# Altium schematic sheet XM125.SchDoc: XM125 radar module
size 420 x 297 mm; CompanyName: Acconeer AB; DrawnBy: Jonas Långbacka; Address1: Acconeer AB; Address2: Västra Varvsgatan 19; Address3: 211 77 Malmö; Address4: Sweden; SheetNumber: 1; SheetTotal: 1
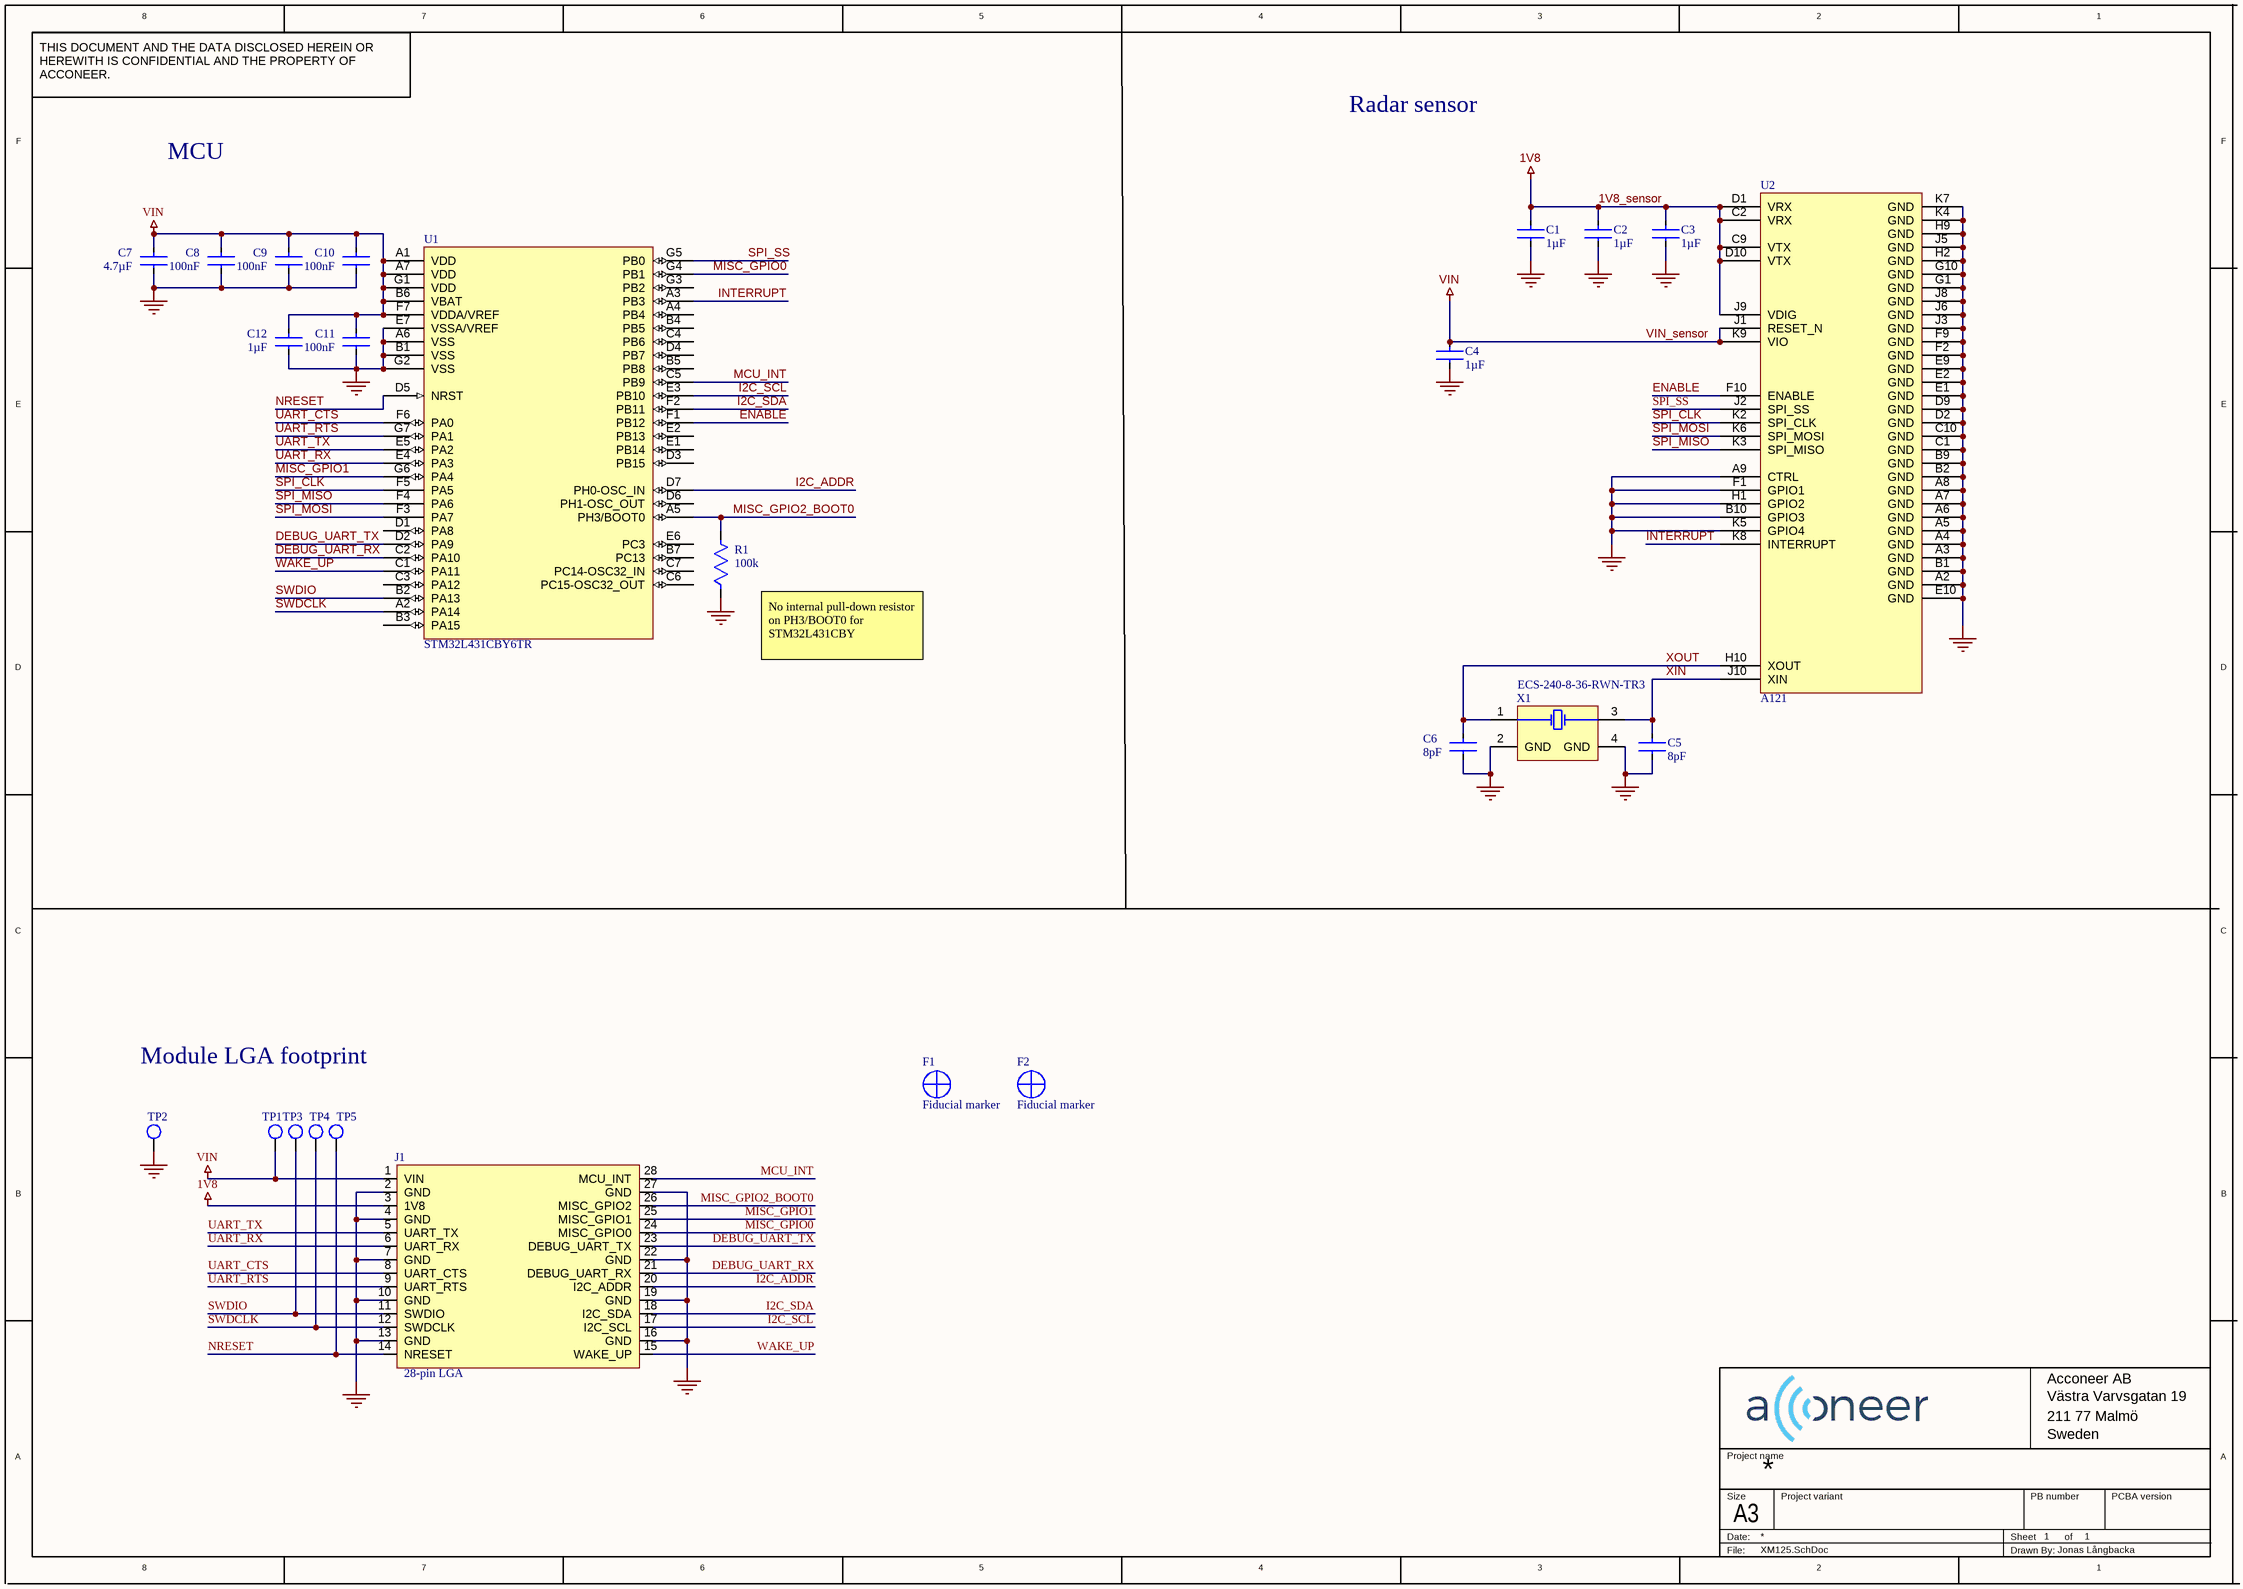
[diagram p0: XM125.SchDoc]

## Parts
C1  value 1µF  [CAPC0603X04L_no_silkscreen]  (hidden comment: Capacitor 1uF, metric 0603)
C2  value 1µF  [CAPC0603X04L_no_silkscreen]  (hidden comment: Capacitor 1uF, metric 0603)
C3  value 1µF  [CAPC0603X04L_no_silkscreen]  (hidden comment: Capacitor 1uF, metric 0603)
C4  value 1µF  [CAPC0603X04L_no_silkscreen]  (hidden comment: Capacitor 1uF, metric 0603)
C5  value 8pF  [CAPC0603X04L_no_silkscreen]  (hidden comment: Capacitor 8pF, metric 0603)
C6  value 8pF  [CAPC0603X04L_no_silkscreen]  (hidden comment: Capacitor 8pF, metric 0603)
C7  value 4.7µF  [CAPC1005X05L]  (hidden comment: Capacitor 4.7uF, metric 1005)
C8  value 100nF  [CAPC0603X04L_no_silkscreen]  (hidden comment: Capacitor 100nF, metric 0603)
C9  value 100nF  [CAPC0603X04L_no_silkscreen]  (hidden comment: Capacitor 100nF, metric 0603)
C10  value 100nF  [CAPC0603X04L_no_silkscreen]  (hidden comment: Capacitor 100nF, metric 0603)
C11  value 100nF  [CAPC0603X04L_no_silkscreen]  (hidden comment: Capacitor 100nF, metric 0603)
C12  value 1µF  [CAPC0603X04L_no_silkscreen]  (hidden comment: Capacitor 1uF, metric 0603)
F1  Fiducial marker  [Fiducial 0.5 mm footprint-1]  (no BOM)
F2  Fiducial marker  [Fiducial 0.5 mm footprint-1]  (no BOM)
J1  28-pin LGA  [LCCS127P1500X1800X0-28N]  (no BOM)
R1  value 100k  [RESC0603X03L_no_silkscreen]  (hidden comment: Resistor 100 kOhm, metric 0603)
TP1  Testpoint  [Testpoint_circular_0.8_no_silkscreen]  (value not drawn)  (no BOM)
TP2  Testpoint  [Testpoint_circular_0.8_no_silkscreen]  (value not drawn)  (no BOM)
TP3  Testpoint  [Testpoint_circular_0.8_no_silkscreen]  (value not drawn)  (no BOM)
TP4  Testpoint  [Testpoint_circular_0.8_no_silkscreen]  (value not drawn)  (no BOM)
TP5  Testpoint  [Testpoint_circular_0.8_no_silkscreen]  (value not drawn)  (no BOM)
U1  STM32L431CBY6TR  [BGA49C40P7X7_314X313X58]
U2  A121  [BGA50C50P10X10_520X550X90]
X1  ECS-240-8-36-RWN-TR3  [ECS-240-8-36-RWN-TR3-Footprint-No-Silk]

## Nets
1V8_sensor: C1.1 C2.1 C3.1 J1.3(1V8) U2.C2(VRX) U2.C9(VTX) U2.D1(VRX) U2.D10(VTX) U2.J9(VDIG)  [also labelled 1V8]
GND: C1.2 C2.2 C3.2 C4.2 C5.2 C6.2 C7.2 C8.2 C9.2 C10.2 C11.2 C12.2 J1.2(GND) J1.4(GND) J1.7(GND) J1.10(GND) J1.13(GND) J1.16(GND) J1.19(GND) J1.22(GND) J1.27(GND) R1.1 TP2.1 U1.A6(VSS) U1.B1(VSS) U1.E7(VSSA/VREF) U1.G2(VSS) U2.A2(GND) U2.A3(GND) U2.A4(GND) U2.A5(GND) U2.A6(GND) U2.A7(GND) U2.A8(GND) U2.A9(CTRL) U2.B1(GND) U2.B2(GND) U2.B9(GND) U2.B10(GPIO3) U2.C1(GND) U2.C10(GND) U2.D2(GND) U2.D9(GND) U2.E1(GND) U2.E2(GND) U2.E9(GND) U2.E10(GND) U2.F1(GPIO1) U2.F2(GND) U2.F9(GND) U2.G1(GND) U2.G10(GND) U2.H1(GPIO2) U2.H2(GND) U2.H9(GND) U2.J3(GND) U2.J5(GND) U2.J6(GND) U2.J8(GND) U2.K4(GND) U2.K5(GPIO4) U2.K7(GND) X1.2(GND) X1.4(GND)
VIN_sensor: C4.1 C7.1 C8.1 C9.1 C10.1 C11.1 C12.1 J1.1(VIN) TP1.1 U1.A1(VDD) U1.A7(VDD) U1.B6(VBAT) U1.F7(VDDA/VREF) U1.G1(VDD) U2.J1(RESET_N) U2.K9(VIO)  [also labelled VIN]
DEBUG_UART_RX: J1.21(DEBUG_UART_RX) U1.C2(PA10)
DEBUG_UART_TX: J1.23(DEBUG_UART_TX) U1.D2(PA9)
ENABLE: U1.F1(PB12) U2.F10(ENABLE)
I2C_ADDR: J1.20(I2C_ADDR) U1.D7(PH0-OSC_IN)
I2C_SCL: J1.17(I2C_SCL) U1.E3(PB10)
I2C_SDA: J1.18(I2C_SDA) U1.F2(PB11)
INTERRUPT: U1.A3(PB3) U2.K8(INTERRUPT)
MCU_INT: J1.28(MCU_INT) U1.C5(PB9)
MISC_GPIO0: J1.24(MISC_GPIO0) U1.G4(PB1)
MISC_GPIO1: J1.25(MISC_GPIO1) U1.G6(PA4)
MISC_GPIO2_BOOT0: J1.26(MISC_GPIO2) R1.2 U1.A5(PH3/BOOT0)
NRESET: J1.14(NRESET) TP5.1 U1.D5(NRST)
SPI_CLK: U1.F5(PA5) U2.K2(SPI_CLK)
SPI_MISO: U1.F4(PA6) U2.K3(SPI_MISO)
SPI_MOSI: U1.F3(PA7) U2.K6(SPI_MOSI)
SPI_SS: U1.G5(PB0) U2.J2(SPI_SS)
SWDCLK: J1.12(SWDCLK) TP4.1 U1.A2(PA14)
SWDIO: J1.11(SWDIO) TP3.1 U1.B2(PA13)
UART_CTS: J1.8(UART_CTS) U1.F6(PA0)
UART_RTS: J1.9(UART_RTS) U1.G7(PA1)
UART_RX: J1.6(UART_RX) U1.E4(PA3)
UART_TX: J1.5(UART_TX) U1.E5(PA2)
WAKE_UP: J1.15(WAKE_UP) U1.C1(PA11)
XIN: C5.1 U2.J10(XIN) X1.3(X2)
XOUT: C6.1 U2.H10(XOUT) X1.1(X1)

Not connected (* = marked no-connect by the designer): F1 1; F2 1; U1 A4(PB4) B3(PA15) B4(PB5) B5(PB8) B7(PC13) C3(PA12) C4(PB6) C6(PC15-OSC32_OUT) C7(PC14-OSC32_IN) D1(PA8) D3(PB15) D4(PB7) D6(PH1-OSC_OUT) E1(PB14) E2(PB13) E6(PC3) G3(PB2)

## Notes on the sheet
- Radar sensor
- MCU
- (near R1) No internal pull-down resistor on PH3/BOOT0 for STM32L431CBY
- Module LGA footprint

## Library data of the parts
C1-C4 C12 = CMP-001-00106-9: Generic 1uF SMD capacitor, metric 0603 (0201); Tolerance: 20%; Voltage Rating: 10V
C5 C6 = CMP-001-00107-7: Generic 8pF SMD capacitor, metric 0603 (0201); Voltage Rating: 10V; Tolerance: 20%; Capacitor Type: Ceramic; Temperature Coefficient: C0G, NP0
C7 = CMP-001-00105-9: Generic 4.7uF SMD capacitor, metric 1005 (0402); Tolerance: 20%; Voltage Rating: 10V
C8-C11 = CMP-001-00119-4: Generic 100 nF SMD capacitor, metric 0603 (0201); Tolerance: 20%; Voltage Rating: 10V
F1 F2 = CMP-00028-00007-12
J1 = CMP-002-00117-37: 28-pin Land Grid Array (LGA), pitch 1.27 mm
R1 = CMP-009-00221-3: 100 kOhm generic SMD resistor, +/-1%, metric 0603 (0201); Tolerance: 1%
TP1-TP5 = CMP-00030-00001-11: Circular test point
U1 = CMP-020-00029-7: RISC Microcontroller, 32-Bit, FLASH, 80MHz, CMOS, PBGA49; Min Supply Voltage: 1.71V; Max Supply Voltage: 3.6V
U2 = CMP-010-00030-4: Acconeer A121 pulsed coherent 60 GHz radar sensor; Manufacturer: Acconeer AB
X1 = CMP-003-00040-8: Crystal 24 MHz 2.5 x 2.0 mm 4-SMD; Manufacturer: ECS Inc.; ESR: 60; Frequency: 24MHz; Load Capacitance: 8pF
